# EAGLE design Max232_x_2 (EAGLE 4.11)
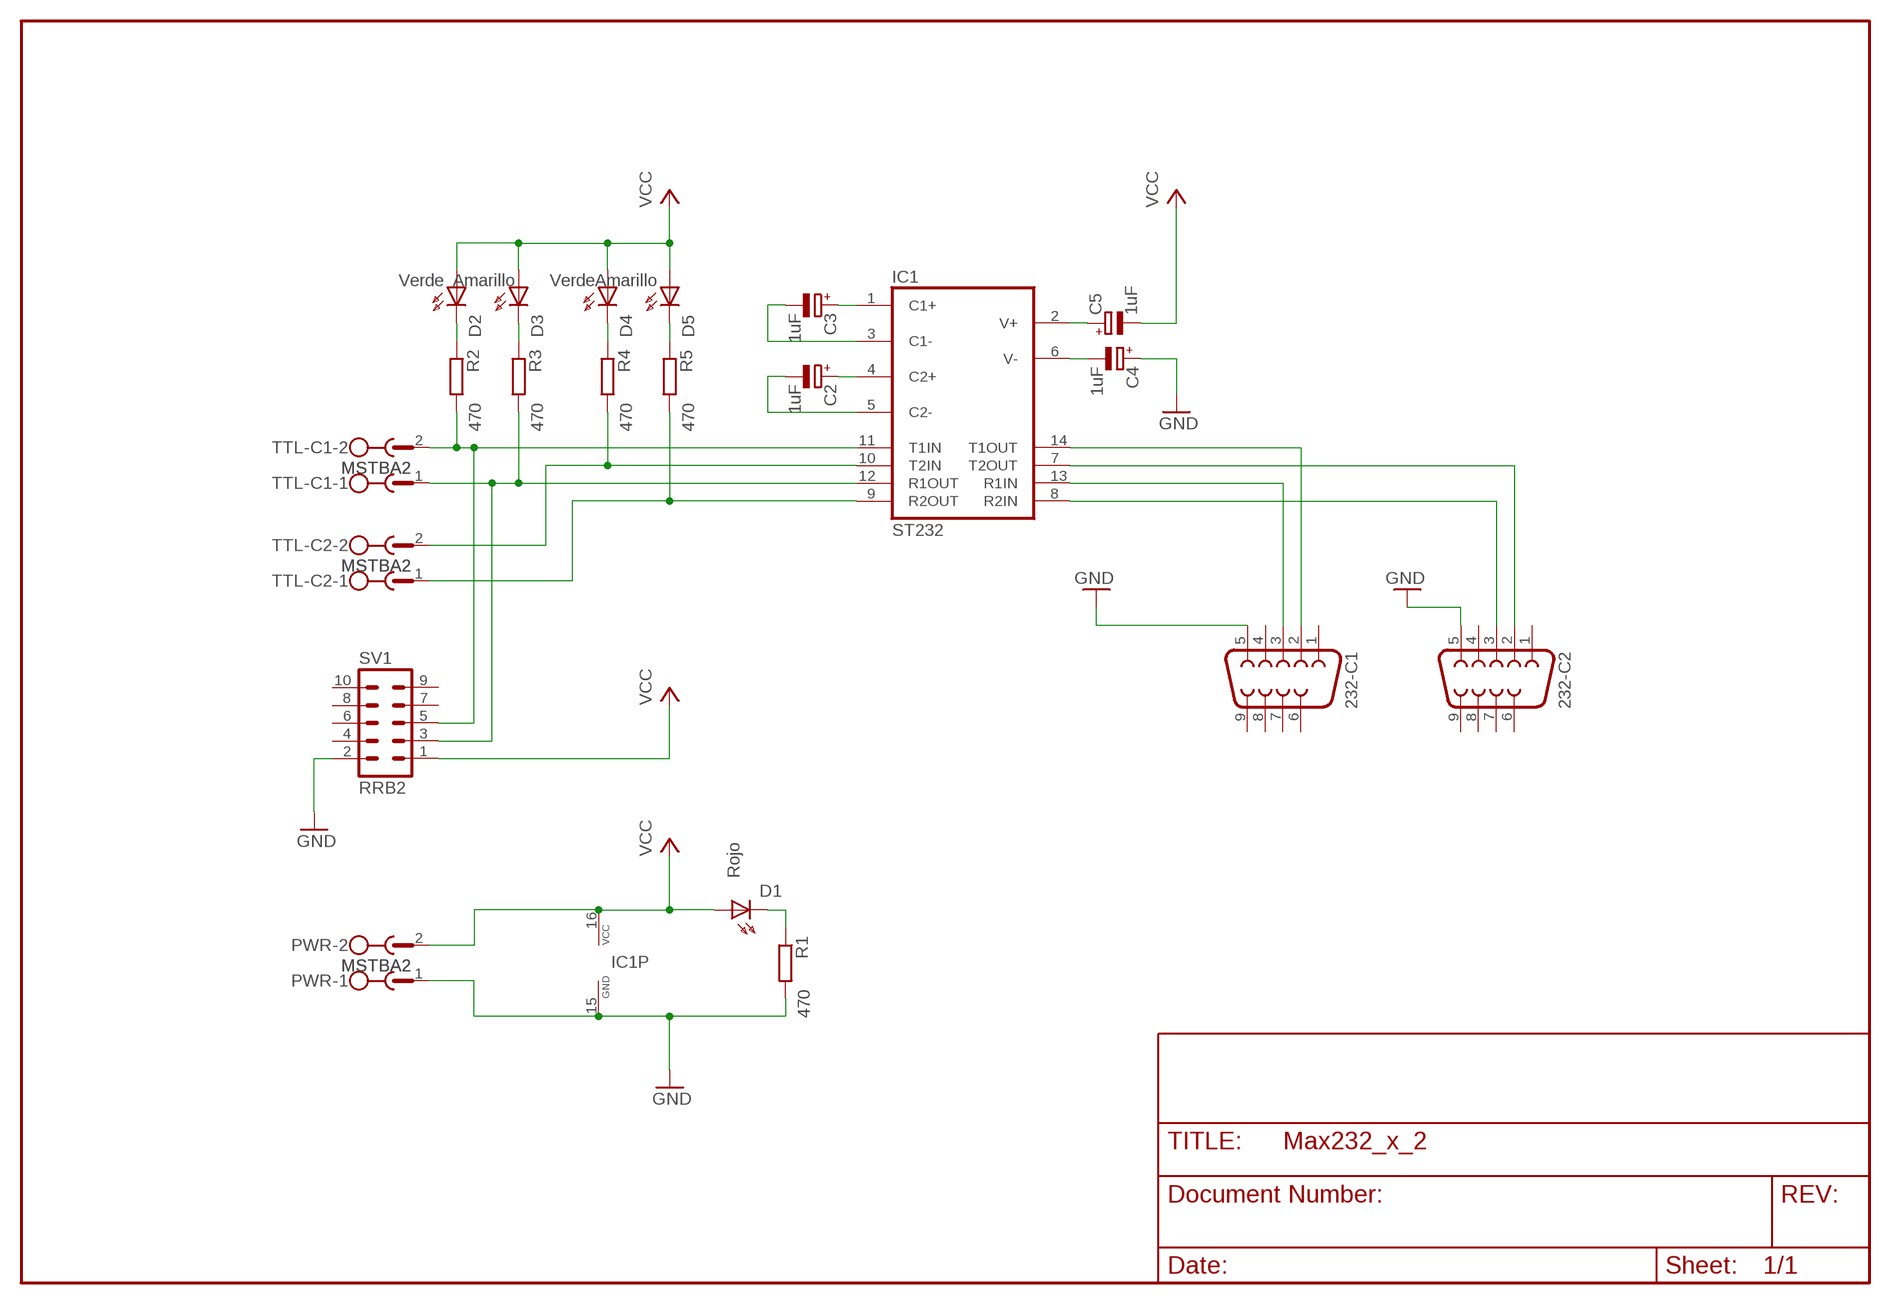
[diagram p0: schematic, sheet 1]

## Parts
232-C1  F09H  [F09H]
232-C2  F09H  [F09H]
C2  1uF  CPOL-EUE1.8-4  [E1,8-4]
C3  1uF  CPOL-EUE1.8-4  [E1,8-4]
C4  1uF  CPOL-EUE1.8-4  [E1,8-4]
C5  1uF  CPOL-EUE1.8-4  [E1,8-4]
D1  Rojo  LED3MM  [LED3MM]
D2  Verde  LED3MM  [LED3MM]
D3  Amarillo  LED3MM  [LED3MM]
D4  Verde  LED3MM  [LED3MM]
D5  Amarillo  LED3MM  [LED3MM]
IC1  ST232  MAX232  [DIL16]
PWR  MSTBA2  [MSTBA2]
R1  470  R-EU_0204/7  [0204/7]
R2  470  R-EU_0204/7  [0204/7]
R3  470  R-EU_0204/7  [0204/7]
R4  470  R-EU_0204/7  [0204/7]
R5  470  R-EU_0204/7  [0204/7]
SV1  RRB2  ML10  [ML10]
TTL-C1  MSTBA2  [MSTBA2]
TTL-C2  MSTBA2  [MSTBA2]

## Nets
232C1RX: 232-C1.3 IC1.13(R1IN)
232C1TX: 232-C1.2 IC1.14(T1OUT)
232C2RX: 232-C2.3 IC1.8(R2IN)
232C2TX: 232-C2.2 IC1.7(T2OUT)
GND: 232-C1.5 232-C2.5 C4.+ IC1.15(GND) PWR.1 R1.2 SV1.2
N$1: IC1.10(T2IN) R4.2 TTL-C2.2
N$2: IC1.9(R2OUT) R5.2 TTL-C2.1
N$4: C3.+ IC1.1(C1+)
N$5: C2.+ IC1.4(C2+)
N$6: C2.- IC1.5(C2-)
N$7: C3.- IC1.3(C1-)
N$8: C5.+ IC1.2(V+)
N$9: C4.- IC1.6(V-)
N$14: D1.K(C) R1.1
N$16: D2.K(C) R2.1
N$17: D3.K(C) R3.1
N$18: D4.K(C) R4.1
N$19: D5.K(C) R5.1
TTLC1RX: IC1.12(R1OUT) R3.2 SV1.3 TTL-C1.1
TTLC1TX: IC1.11(T1IN) R2.2 SV1.5 TTL-C1.2
VCC: C5.- D1.A D2.A D3.A D4.A D5.A IC1.16(VCC) PWR.2 SV1.1
Unconnected: 232-C1.1 232-C1.4 232-C1.6 232-C1.7 232-C1.8 232-C1.9 232-C2.1 232-C2.4 232-C2.6 232-C2.7 232-C2.8 232-C2.9 SV1.4 SV1.6 SV1.7 SV1.8 SV1.9 SV1.10

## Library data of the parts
232-C1 232-C2 = con-subd:F09: SUB-D
C2-C5 = rcl:CPOL-EU: POLARIZED CAPACITOR, European symbol
D1-D5 = led:LED3MM: LED
IC1 = maxim:MAX232: RS232 TRANSEIVER
PWR TTL-C1 TTL-C2 = con-phoenix-508:MSTBA2: PHOENIX
R1-R5 = rcl:R-EU_: RESISTOR, European symbol
SV1 = con-ml:ML10: HARTING

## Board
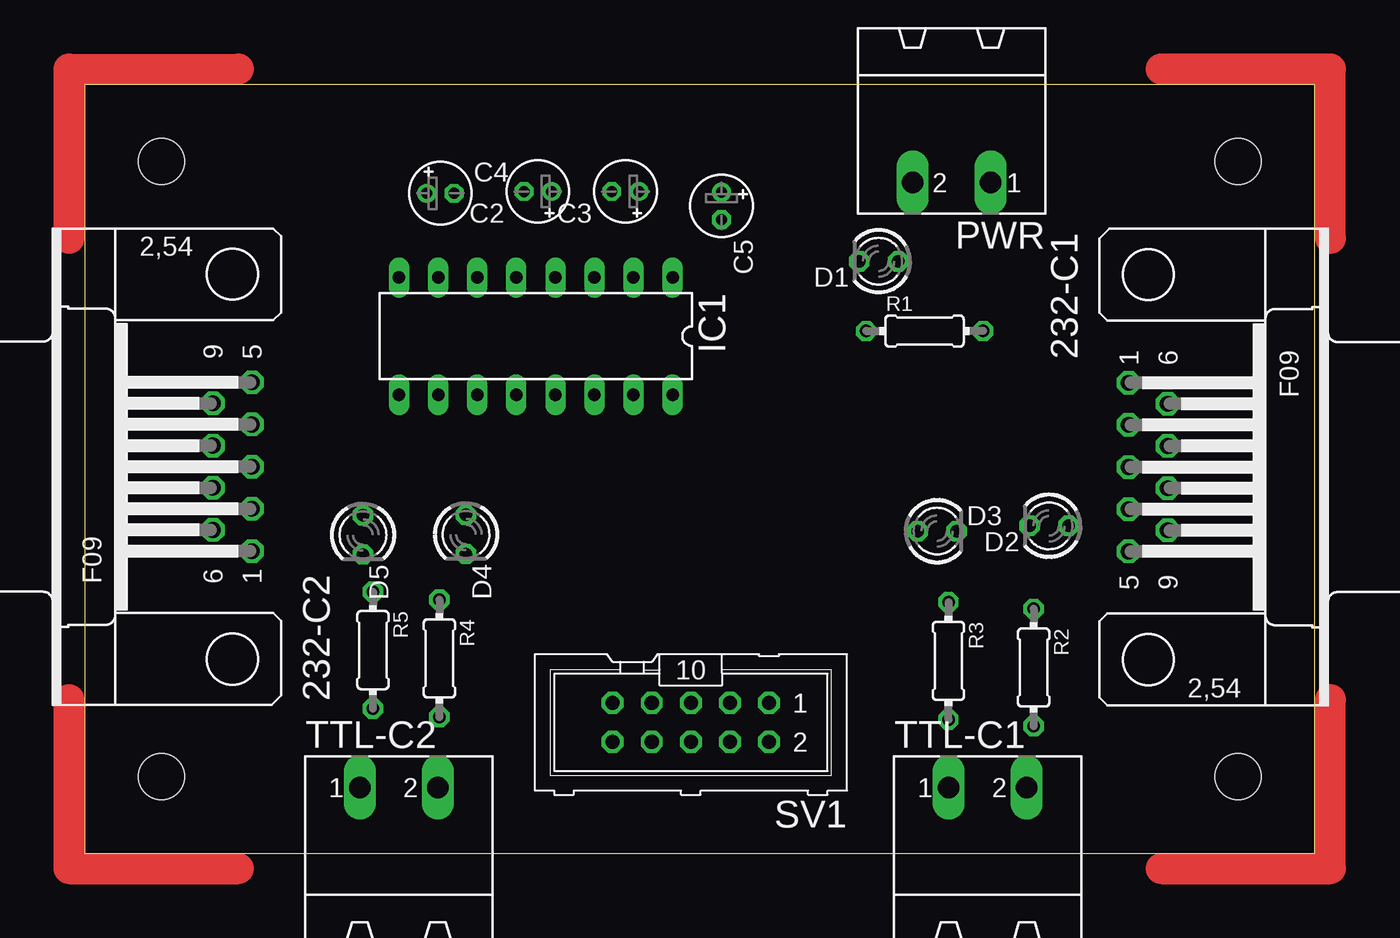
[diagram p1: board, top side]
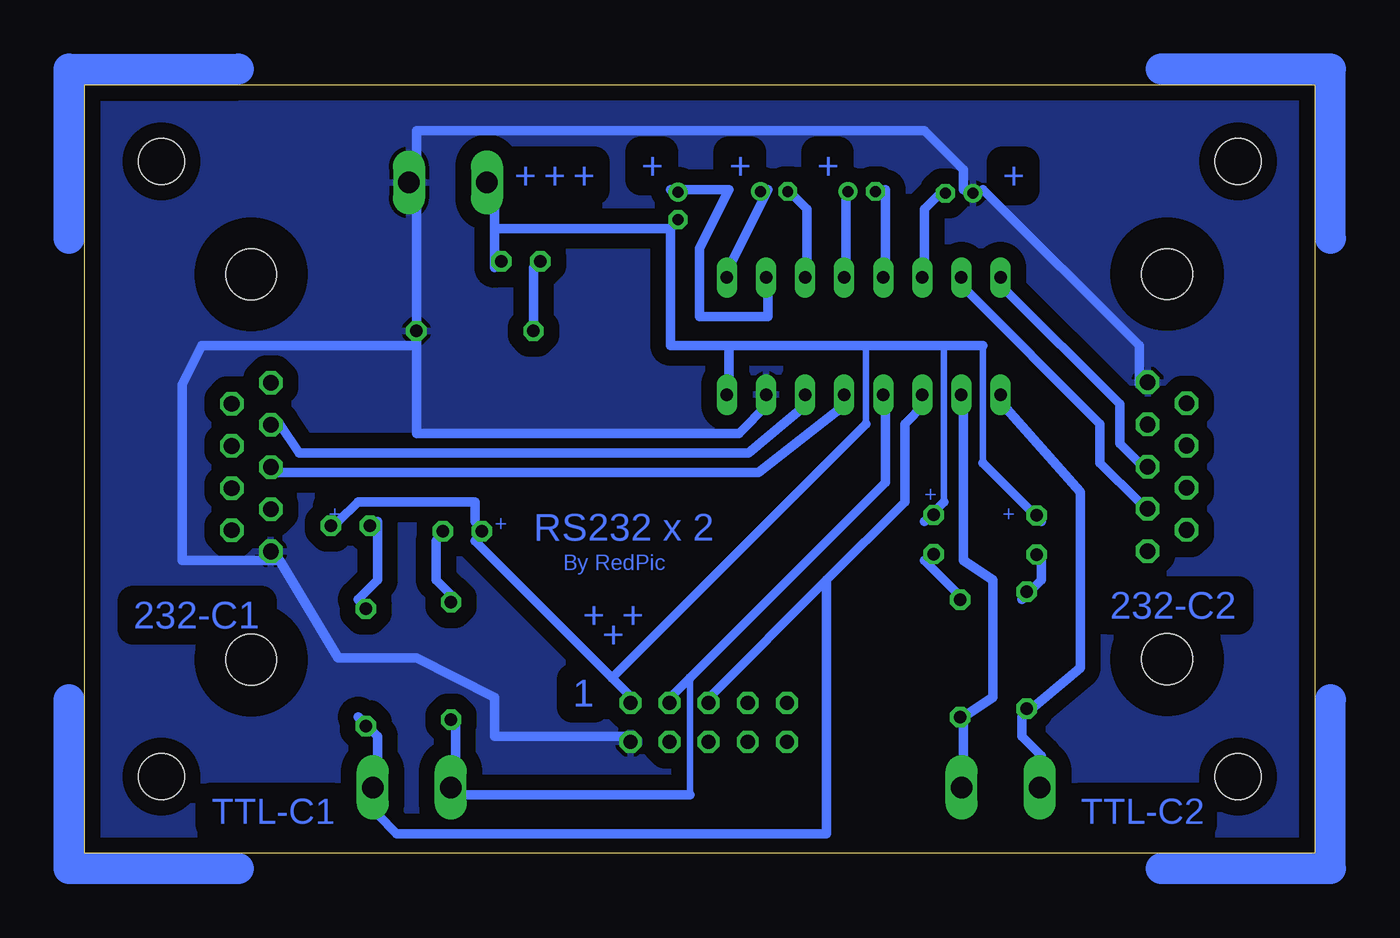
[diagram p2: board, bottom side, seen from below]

Size 80 x 50 mm. Coordinates in mm from the lower left corner, seen from the top.
Outline: 0,0 80,0 80,50 0,50 0,0
Copper layers (1*16): Top 0.035mm / dielectric 1.5mm / Bottom 0.035mm
Design rules "default": minimum track width 10mil, minimum drill 24mil, track to track 8mil, track to pad 8mil, pad to pad 8mil, via to via 8mil, smd to smd 8mil, copper to edge 20mil, drill to drill 8mil, minimum pad ring 10mil, minimum via ring 8mil, stop-mask expansion 4mil, vias tented up to drill 0mil, thermal gap 10mil
Holes 3 mm at 5,5 75,5 5,45 75,45

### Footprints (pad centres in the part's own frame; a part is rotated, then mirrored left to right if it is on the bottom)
F09H = drill 1.016 octagon: 1 -5.486,-1.27; 2 -2.743,-1.27; 3 0,-1.27; 4 2.743,-1.27; 5 5.486,-1.27; 6 -4.115,1.27; 7 -1.372,1.27; 8 1.372,1.27; 9 4.115,1.27 | hole 3.302: -12.522,0; 12.522,0
E1,8-4 = drill 0.711 pad 1.168 round: + -0.889,0 | drill 0.711 pad 1.168 octagon: - 0.889,0
LED3MM = drill 0.813 octagon: A -1.27,0; K 1.27,0
DIL16 = drill 0.813 long: 1 -8.89,-3.81; 2 -6.35,-3.81; 3 -3.81,-3.81; 4 -1.27,-3.81; 5 1.27,-3.81; 6 3.81,-3.81; 7 6.35,-3.81; 8 8.89,-3.81; 9 8.89,3.81; 10 6.35,3.81; 11 3.81,3.81; 12 1.27,3.81; 13 -1.27,3.81; 14 -3.81,3.81; 15 -6.35,3.81; 16 -8.89,3.81
MSTBA2 = drill 1.397 long: 1 -2.54,5.08; 2 2.54,5.08
0204/7 = drill 0.813 octagon: 1 -3.81,0; 2 3.81,0
ML10 = drill 0.914 octagon: 1 -5.08,-1.27; 2 -5.08,1.27; 3 -2.54,-1.27; 4 -2.54,1.27; 5 0,-1.27; 6 0,1.27; 7 2.54,-1.27; 8 2.54,1.27; 9 5.08,-1.27; 10 5.08,1.27

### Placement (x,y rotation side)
232-C1  69.16,25.13 270 top
232-C2  9.61,25.15 90 top
C2  29.47,43.05 180 top
C3  35.17,43.05 180 top
C4  23.13,42.93 0 top
C5  41.42,42.11 270 top
D1  51.63,38.51 180 top
D2  62.71,21.3 180 top
D3  55.43,20.96 0 top
D4  24.8,20.74 270 top
D5  18.1,20.71 270 top
IC1  29.34,33.64 180 top
PWR  56.37,48.71 180 top
R1  54.62,33.97 0 top
R2  61.71,12.09 270 top
R3  56.17,12.52 270 top
R4  23.07,12.68 270 top
R5  18.75,13.22 270 top
SV1  39.42,8.52 180 top
TTL-C1  58.73,-0.79 0 top
TTL-C2  20.44,-0.79 0 top

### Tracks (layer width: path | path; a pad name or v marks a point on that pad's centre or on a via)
232C1RX
  Bottom 0.61: IC1.13 30.48,29.21 36.2,24.77 67.94,24.77 232-C1.3
232C1TX
  Bottom 0.61: IC1.14 33.02,29.21 36.83,26.04 66.04,26.04 67.31,27.94 232-C1.2
232C2RX
  Bottom 0.61: IC1.8 20.32,36.83 12.7,29.21 12.7,26.67 11.43,25.4 232-C2.3
232C2TX
  Bottom 0.61: IC1.7 22.86,36.83 13.97,27.94 13.97,25.4 11.43,22.86 232-C2.2
GND
  Bottom 0.61: 232-C2.5 11.43,30.48 11.43,33.02 21.59,43.18 C4.+ 22.86,43.18 22.86,44.45 25.4,46.99 58.42,46.99 58.42,44.45 PWR.1 58.42,41.91 58.42,34.29 | 58.42,34.29 58.42,33.02 | 58.42,33.02 58.42,27.3 37.47,27.3 35.56,29.21 IC1.15 | 58.42,33.02 72.39,33.02 73.66,30.48 73.66,19.05 67.31,19.05 63.5,12.7 58.42,12.7 53.34,10.16 53.34,7.62 44.45,7.62 SV1.2 | 58.42,34.29 R1.2
  pour Bottom (isolate 1.016): 80.01,49.53 0,49.53 0,0 80.01,0
N$1
  Bottom 0.61: 22.86,8.89 22.86,6.35 TTL-C2.2 | 22.86,8.89 20.95,10.16 20.95,17.78 22.86,19.05 22.86,29.21 IC1.10 | 22.86,8.89 R4.2
N$2
  Bottom 0.61: 19.05,8.89 19.05,7.62 17.78,6.35 TTL-C2.1 | 19.05,8.89 15.24,12.06 15.24,23.5 20.32,29.21 IC1.9 | 19.05,8.89 R5.2
N$3
  Top 2: 10,-1 -1,-1 -1,10
N$4
  Bottom 0.61: C3.+ 35.56,43.18 38.1,38.1 IC1.1
N$5
  Bottom 0.61: C2.+ 30.48,43.18 30.48,38.1 IC1.4
N$6
  Bottom 0.61: C2.- 27.94,43.18 27.94,38.1 IC1.5
N$7
  Bottom 0.61: C3.- 34.29,43.18 33.02,41.91 33.02,38.1 IC1.3
N$8
  Bottom 0.61: C5.+ 41.91,43.18 38.1,43.18 40.01,39.37 40.01,34.92 35.56,34.92 35.56,36.83 IC1.2
N$9
  Bottom 0.61: C4.- 24.13,43.18 25.4,41.91 25.4,38.1 IC1.6
N$10
  Top 2: 70,-1 81,-1 81,10
N$11
  Top 2: 10,51 -1,51 -1,40
N$12
  Top 2: 81,40 81,51 70,51
N$13
  Bottom 2: 10,-1 -1,-1 -1,10
N$14
  Bottom 0.61: D1.K 50.8,38.1 50.8,34.29 R1.1
N$15
  Bottom 2: 70,-1 81,-1 81,10
N$16
  Bottom 0.61: R2.1 62.23,16.51 60.96,17.78 60.96,21.59 D2.K
N$17
  Bottom 0.61: R3.1 55.88,16.51 57.15,17.78 57.15,20.32 D3.K
N$18
  Bottom 0.61: R4.1 22.86,16.51 25.4,19.05 D4.K
N$19
  Bottom 0.61: R5.1 19.05,16.51 17.78,17.78 17.78,19.05 D5.K
N$20
  Bottom 2: 10,51 -1,51 -1,40
N$21
  Bottom 2: 81,40 81,51 70,51
TTLC1RX
  Bottom 0.406: 40.64,3.81 40.64,11.43
  Bottom 0.61: R3.2 55.88,8.89 55.88,6.35 TTL-C1.1 55.88,3.81 40.64,3.81 | IC1.12 27.94,29.21 27.94,24.13 40.64,11.43 41.91,10.16 SV1.3
TTLC1TX
  Bottom 0.61: R2.2 62.23,8.89 60.96,7.62 60.96,6.35 TTL-C1.2 60.96,2.54 59.7,1.26 57.15,1.27 31.75,1.27 31.75,17.78 | 31.75,17.78 39.37,10.16 SV1.5 | 31.75,17.78 26.67,22.86 26.67,27.94 25.4,29.21 IC1.11
VCC
  Bottom 0.406: 21.59,25.4 21.59,33.02 | 24.13,33.02 24.13,22.86 | 29.21,33.02 29.21,27.94
  Bottom 0.61: 45.72,11.43 44.45,10.16 SV1.1 | 45.72,11.43 54.61,20.32 D3.A 54.61,21.59 54.61,22.86 62.23,22.86 63.5,21.59 D2.A | 41.91,40.64 53.34,40.64 | 53.34,40.64 53.34,41.91 PWR.2 | 53.34,40.64 53.34,38.1 D1.A | 21.59,25.4 17.78,21.59 D5.A | 38.1,33.02 29.21,33.02 24.13,33.02 21.59,33.02 | 38.1,33.02 38.1,30.48 IC1.16 | 24.13,22.86 25.4,21.59 D4.A | 41.91,40.64 41.91,33.02 38.1,33.02 | 41.91,40.64 C5.- | 29.21,27.94 45.72,11.43

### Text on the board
Bottom: O | + | + | + | O | + | + | + | + | O | O | + | + | + | + | RS232 x 2 | By RedPic | 232-C2 | + | + | 232-C1 | + | O | O | 1 | O | O | TTL-C2 | TTL-C1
